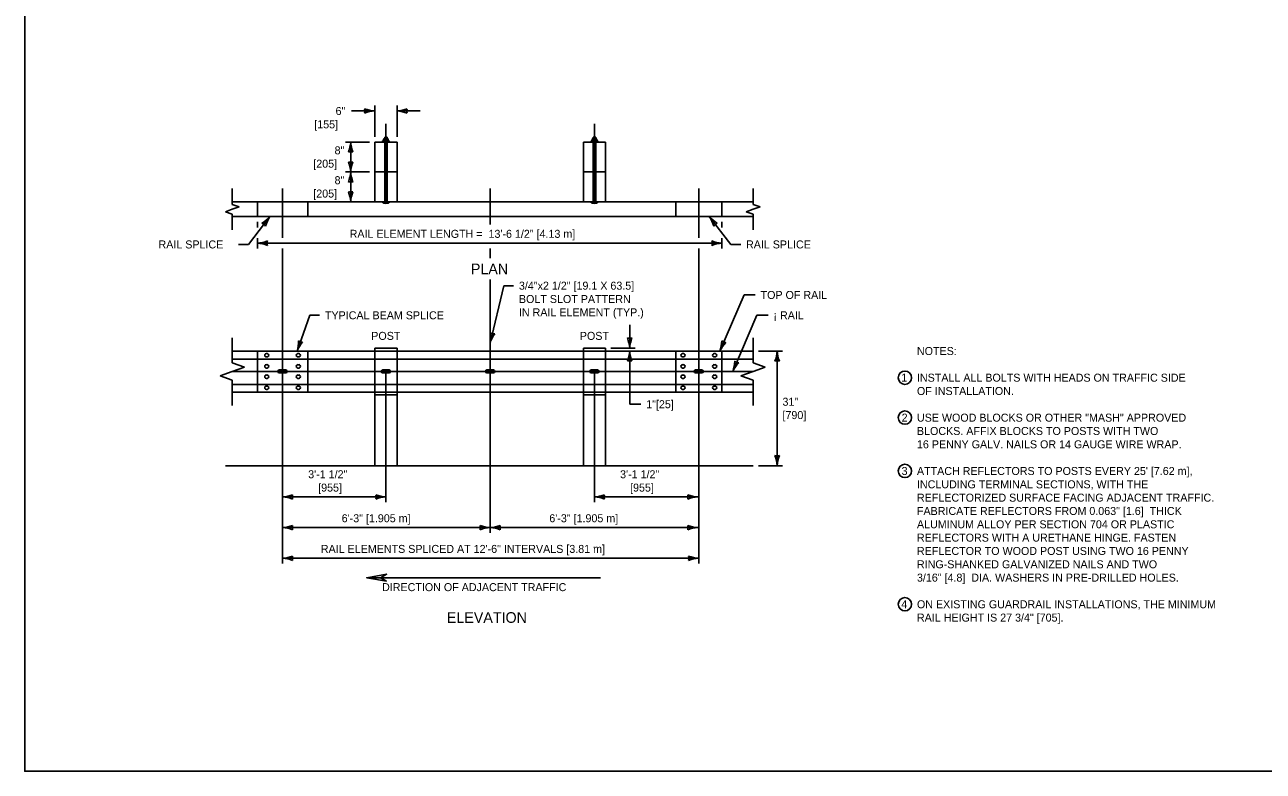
# Model space of a CAD drawing. Extents: x 49991.4 to 50021, y 49987.6 to 50011.4.
# Drawn here: x 49999.38 to 50008.67, y 49987.8 to 49993.4 of the extents above; entities that cross this region are included whole.
import ezdxf

# ---------------------------------------------------------------- set-up
doc = ezdxf.new("R2010")
doc.units = 0
for name, color, linetype in [('Level 1', 7, 'Continuous'), ('Level 2', 7, 'Continuous'), ('Level 3', 7, 'Continuous'), ('Level 4', 7, 'Continuous'), ('Level 5', 7, 'Continuous'), ('Level 6', 7, 'Continuous')]:
    doc.layers.add(name, color=color, linetype=linetype)

msp = doc.modelspace()

# ---------------------------------------------------------------- linework, layer by layer
at = {"layer": 'Level 1'}
for p, q in [((50002.008, 49992.0707), (50002.008, 49992.5187)), ((50002.1746, 49992.5187), (50002.008, 49992.5187)), ((50002.1158, 49992.5278), (50002.067, 49992.5278)), ((50002.067, 49992.5278), (50002.067, 49992.5187)), ((50002.0733, 49992.5278), (50002.0733, 49992.5412)), ((50002.1045, 49992.5439), (50002.0784, 49992.544)), ((50002.1005, 49992.5554), (50002.0822, 49992.5554)), ((50002.0822, 49992.544), (50002.0822, 49992.5554)), ((50002.1005, 49992.5543), (50002.0822, 49992.5534)), ((50002.1005, 49992.5502), (50002.0822, 49992.5493)), ((50002.1005, 49992.5466), (50002.0822, 49992.5457)), ((50002.0834, 49992.5278), (50002.0834, 49992.5413)), ((50002.0996, 49992.5278), (50002.0996, 49992.5414)), ((50002.1005, 49992.5439), (50002.1005, 49992.5554)), ((50002.1095, 49992.5415), (50002.1095, 49992.5278)), ((50002.1158, 49992.5278), (50002.1158, 49992.5187)), ((50002.1746, 49992.0707), (50002.1746, 49992.5187)), ((50003.5719, 49992.0707), (50003.5719, 49992.5187)), ((50003.5719, 49992.5187), (50003.7385, 49992.5187)), ((50003.6307, 49992.5278), (50003.6795, 49992.5278)), ((50003.6307, 49992.5278), (50003.6307, 49992.5187)), ((50003.637, 49992.5415), (50003.637, 49992.5278)), ((50003.6419, 49992.5439), (50003.668, 49992.544)), ((50003.646, 49992.5554), (50003.6643, 49992.5554)), ((50003.646, 49992.5439), (50003.646, 49992.5554)), ((50003.646, 49992.5543), (50003.6643, 49992.5534)), ((50003.646, 49992.5502), (50003.6643, 49992.5493)), ((50003.646, 49992.5466), (50003.6643, 49992.5457)), ((50003.6469, 49992.5278), (50003.6469, 49992.5414)), ((50003.663, 49992.5278), (50003.663, 49992.5413)), ((50003.6643, 49992.544), (50003.6643, 49992.5554)), ((50003.6732, 49992.5278), (50003.6732, 49992.5412)), ((50003.6795, 49992.5278), (50003.6795, 49992.5187)), ((50003.7385, 49992.0707), (50003.7385, 49992.5187)), ((50002.1746, 49992.2947), (50002.008, 49992.2947)), ((50003.5719, 49992.2947), (50003.7385, 49992.2947)), ((50000.9397, 49992.0707), (50004.8443, 49992.0707)), ((50001.1274, 49992.0707), (50001.1274, 49991.9597)), ((50004.2645, 49992.0707), (50004.2645, 49991.9597)), ((50000.9397, 49991.9597), (50004.8443, 49991.9597)), ((50004.8443, 49990.9514), (50000.9397, 49990.9514)), ((50001.1274, 49990.6438), (50001.1274, 49990.9514)), ((50001.201, 49990.9321), (50001.195, 49990.9321)), ((50001.201, 49990.9069), (50001.195, 49990.9069)), ((50001.4381, 49990.9321), (50001.4321, 49990.9321)), ((50001.4381, 49990.9069), (50001.4321, 49990.9069)), ((50002.1747, 49990.9734), (50002.0081, 49990.9734)), ((50002.0081, 49990.9734), (50002.0081, 49990.9514)), ((50002.1747, 49990.9734), (50002.1747, 49990.9514)), ((50003.7384, 49990.9734), (50003.5718, 49990.9734)), ((50003.5718, 49990.9734), (50003.5718, 49990.9514)), ((50003.7384, 49990.9734), (50003.7384, 49990.9514)), ((50004.2645, 49990.6438), (50004.2645, 49990.9514)), ((50004.322, 49990.9321), (50004.316, 49990.9321)), ((50004.322, 49990.9069), (50004.316, 49990.9069)), ((50004.5591, 49990.9321), (50004.5531, 49990.9321)), ((50004.5591, 49990.9069), (50004.5531, 49990.9069)), ((50004.8443, 49990.8913), (50000.9397, 49990.8913)), ((50001.201, 49990.8489), (50001.195, 49990.8489)), ((50001.201, 49990.8238), (50001.195, 49990.8238)), ((50001.2918, 49990.8092), (50001.3404, 49990.8092)), ((50001.4381, 49990.8489), (50001.4321, 49990.8489)), ((50001.4381, 49990.8238), (50001.4321, 49990.8238)), ((50002.0671, 49990.8092), (50002.1157, 49990.8092)), ((50002.8488, 49990.8092), (50002.8975, 49990.8092)), ((50003.6306, 49990.8092), (50003.6792, 49990.8092)), ((50004.322, 49990.8489), (50004.316, 49990.8489)), ((50004.322, 49990.8238), (50004.316, 49990.8238)), ((50004.4128, 49990.8092), (50004.4614, 49990.8092)), ((50004.5591, 49990.8489), (50004.5531, 49990.8489)), ((50004.5591, 49990.8238), (50004.5531, 49990.8238)), ((50001.201, 49990.7714), (50001.195, 49990.7714)), ((50001.201, 49990.7463), (50001.195, 49990.7463)), ((50001.2918, 49990.7884), (50001.3404, 49990.7884)), ((50001.4381, 49990.7714), (50001.4321, 49990.7714)), ((50001.4381, 49990.7463), (50001.4321, 49990.7463)), ((50002.0671, 49990.7884), (50002.1157, 49990.7884)), ((50002.8488, 49990.7884), (50002.8975, 49990.7884)), ((50003.6306, 49990.7884), (50003.6792, 49990.7884)), ((50004.322, 49990.7714), (50004.316, 49990.7714)), ((50004.322, 49990.7463), (50004.316, 49990.7463)), ((50004.4128, 49990.7884), (50004.4614, 49990.7884)), ((50004.5591, 49990.7714), (50004.5531, 49990.7714)), ((50004.5591, 49990.7463), (50004.5531, 49990.7463)), ((50004.8443, 49990.7013), (50000.9397, 49990.7013)), ((50004.8443, 49990.6438), (50000.9397, 49990.6438)), ((50001.201, 49990.6883), (50001.195, 49990.6883)), ((50001.201, 49990.6631), (50001.195, 49990.6631)), ((50001.4381, 49990.6883), (50001.4321, 49990.6883)), ((50001.4381, 49990.6631), (50001.4321, 49990.6631)), ((50002.0081, 49990.6438), (50002.0081, 49990.0903)), ((50002.1747, 49990.6218), (50002.0081, 49990.6218)), ((50002.1747, 49990.6438), (50002.1747, 49990.0903)), ((50003.5718, 49990.6438), (50003.5718, 49990.0903)), ((50003.7384, 49990.6218), (50003.5718, 49990.6218)), ((50003.7384, 49990.6438), (50003.7384, 49990.0903)), ((50004.322, 49990.6883), (50004.316, 49990.6883)), ((50004.322, 49990.6631), (50004.316, 49990.6631)), ((50004.5591, 49990.6883), (50004.5531, 49990.6883)), ((50004.5591, 49990.6631), (50004.5531, 49990.6631)), ((50000.8893, 49990.0903), (50004.8443, 49990.0903))]:
    msp.add_line(p, q, dxfattribs=at)
msp.add_lwpolyline([(49999.3835, 49998.9992), (50016.7501, 49998.9992), (50016.7501, 49987.7988), (49999.3835, 49987.7988)], close=True, dxfattribs=at)
for centre, radius, start, end in [((50002.0784, 49992.5379), 0.00606, 33.88707, 147.47731), ((50002.0915, 49992.5301), 0.0138, 54.60759, 125.9383), ((50002.1046, 49992.5377), 0.00626, 38.23957, 143.50603), ((50003.6419, 49992.5377), 0.00626, 36.49397, 141.76043), ((50003.6549, 49992.5301), 0.0138, 54.0617, 125.39241), ((50003.6681, 49992.5379), 0.00606, 32.52269, 146.11293), ((50001.2918, 49990.7988), 0.0104, 90, 180), ((50001.3404, 49990.7988), 0.0104, 360, 90), ((50002.0671, 49990.7988), 0.0104, 90, 180), ((50002.1157, 49990.7988), 0.0104, 360, 90), ((50002.8488, 49990.7988), 0.0104, 90, 180), ((50002.8975, 49990.7988), 0.0104, 360, 90), ((50003.6306, 49990.7988), 0.0104, 90, 180), ((50003.6792, 49990.7988), 0.0104, 360, 90), ((50004.4128, 49990.7988), 0.0104, 90, 180), ((50004.4614, 49990.7988), 0.0104, 360, 90), ((50001.2918, 49990.7988), 0.0104, 180, 270), ((50001.3404, 49990.7988), 0.0104, 270, 0), ((50002.0671, 49990.7988), 0.0104, 180, 270), ((50002.1157, 49990.7988), 0.0104, 270, 0), ((50002.8488, 49990.7988), 0.0104, 180, 270), ((50002.8975, 49990.7988), 0.0104, 270, 0), ((50003.6306, 49990.7988), 0.0104, 180, 270), ((50003.6792, 49990.7988), 0.0104, 270, 0), ((50004.4128, 49990.7988), 0.0104, 180, 270), ((50004.4614, 49990.7988), 0.0104, 270, 0)]:
    msp.add_arc(centre, radius, start, end, dxfattribs=at)
for centre, start_param, end_param in [((50001.195, 49990.9195), 1.570796, 4.712389), ((50001.201, 49990.9195), 4.712389, 7.853982), ((50001.4321, 49990.9195), 1.570796, 4.712389), ((50001.4381, 49990.9195), 4.712389, 7.853982), ((50004.316, 49990.9195), 1.570796, 4.712389), ((50004.322, 49990.9195), 4.712389, 7.853982), ((50004.5531, 49990.9195), 1.570796, 4.712389), ((50004.5591, 49990.9195), 4.712389, 7.853982), ((50001.195, 49990.8364), 1.570796, 4.712389), ((50001.201, 49990.8364), 4.712389, 7.853982), ((50001.4321, 49990.8364), 1.570796, 4.712389), ((50001.4381, 49990.8364), 4.712389, 7.853982), ((50004.316, 49990.8364), 1.570796, 4.712389), ((50004.322, 49990.8364), 4.712389, 7.853982), ((50004.5531, 49990.8364), 1.570796, 4.712389), ((50004.5591, 49990.8364), 4.712389, 7.853982), ((50001.195, 49990.7589), 1.570796, 4.712389), ((50001.201, 49990.7589), 4.712389, 7.853982), ((50001.4321, 49990.7589), 1.570796, 4.712389), ((50001.4381, 49990.7589), 4.712389, 7.853982), ((50004.316, 49990.7589), 1.570796, 4.712389), ((50004.322, 49990.7589), 4.712389, 7.853982), ((50004.5531, 49990.7589), 1.570796, 4.712389), ((50004.5591, 49990.7589), 4.712389, 7.853982), ((50001.195, 49990.6757), 1.570796, 4.712389), ((50001.201, 49990.6757), 4.712389, 7.853982), ((50001.4321, 49990.6757), 1.570796, 4.712389), ((50001.4381, 49990.6757), 4.712389, 7.853982), ((50004.316, 49990.6757), 1.570796, 4.712389), ((50004.322, 49990.6757), 4.712389, 7.853982), ((50004.5531, 49990.6757), 1.570796, 4.712389), ((50004.5591, 49990.6757), 4.712389, 7.853982)]:
    msp.add_ellipse(centre, major_axis=(0.0126, 0), ratio=0.998676, start_param=start_param, end_param=end_param, dxfattribs=at)
at = {"layer": 'Level 2'}
for centre in [(50005.9833, 49990.7514), (50005.9833, 49990.4515), (50005.9833, 49990.0514), (50005.9833, 49989.0514)]:
    msp.add_circle(centre, 0.05, dxfattribs=at)
at = {"layer": 'Level 3'}
for p, q in [((50002.008, 49992.5587), (50002.008, 49992.7921)), ((50002.1746, 49992.5587), (50002.1746, 49992.7921)), ((50001.8346, 49992.7521), (50002.008, 49992.7521)), ((50002.1746, 49992.7521), (50002.348, 49992.7521)), ((50001.9681, 49992.5187), (50001.7873, 49992.5187)), ((50001.8273, 49992.5187), (50001.8273, 49992.2947)), ((50001.9681, 49992.2947), (50001.7872, 49992.2947)), ((50001.8273, 49992.2947), (50001.8273, 49992.0707)), ((50001.0608, 49991.751), (50001.2221, 49991.9597)), ((50001.1274, 49991.9197), (50001.1274, 49991.8772)), ((50004.6777, 49991.751), (50004.5164, 49991.9597)), ((50004.6111, 49991.9197), (50004.6111, 49991.8772)), ((50000.9867, 49991.751), (50001.0608, 49991.751)), ((50001.1274, 49991.7972), (50001.1274, 49991.7205)), ((50001.1274, 49991.7605), (50004.6111, 49991.7605)), ((50004.6111, 49991.7972), (50004.6111, 49991.7205)), ((50004.7517, 49991.751), (50004.6777, 49991.751)), ((50002.9748, 49991.4415), (50002.8732, 49991.0106)), ((50003.0489, 49991.4415), (50002.9748, 49991.4415)), ((50004.7768, 49991.3719), (50004.5952, 49990.9514)), ((50004.8608, 49991.3719), (50004.7768, 49991.3719)), ((50001.5203, 49991.2193), (50001.4255, 49990.9514)), ((50001.5942, 49991.2193), (50001.5203, 49991.2193)), ((50004.8734, 49991.2193), (50004.6918, 49990.7988)), ((50004.9574, 49991.2193), (50004.8734, 49991.2193)), ((50003.9193, 49990.9734), (50003.9193, 49991.1468)), ((50003.7784, 49990.9734), (50003.9593, 49990.9734)), ((50003.9193, 49990.9514), (50003.9193, 49990.5523)), ((50004.8843, 49990.9514), (50005.0651, 49990.9514)), ((50005.0251, 49990.0903), (50005.0251, 49990.9514)), ((50005.0251, 49990.681), (50005.0251, 49990.0903)), ((50004.0033, 49990.5523), (50003.9193, 49990.5523)), ((50004.8843, 49990.0903), (50005.0651, 49990.0903)), ((50001.3161, 49989.8567), (50002.0914, 49989.8567)), ((50004.4302, 49989.8567), (50003.6549, 49989.8567)), ((50001.3161, 49989.6267), (50002.8732, 49989.6267)), ((50002.8732, 49989.6267), (50004.4302, 49989.6267)), ((50001.3161, 49989.3967), (50004.4371, 49989.3967)), ((50003.701, 49989.2499), (50001.9479, 49989.2499))]:
    msp.add_line(p, q, dxfattribs=at)
msp.add_lwpolyline([(50002.0968, 49989.2237), (50001.9479, 49989.2499), (50002.0968, 49989.2763), (50002.0514, 49989.2499)], close=True, dxfattribs=at)
for centre, radius, start, end in [((50001.8798, 49992.7521), 0.0548, 342.13882, 17.86118), ((50002.0195, 49992.9848), 0.233, 247.92284, 267.17269), ((50002.1654, 49992.9742), 0.2223, 272.36048, 292.54399), ((50002.3028, 49992.7521), 0.0548, 162.13882, 197.86118), ((50002.0171, 49992.53), 0.2223, 92.36048, 112.54399), ((50002.1631, 49992.5194), 0.233, 67.92284, 87.17269), ((50001.5945, 49992.5302), 0.233, 337.92284, 357.17269), ((50002.0494, 49992.5278), 0.2223, 182.36048, 202.54399), ((50001.8273, 49992.3904), 0.0548, 72.13882, 107.86118), ((50001.6051, 49992.2855), 0.2223, 2.36048, 22.54399), ((50001.8273, 49992.4229), 0.0548, 252.13882, 287.86118), ((50001.5945, 49992.3062), 0.233, 337.92284, 357.17269), ((50002.06, 49992.2832), 0.233, 157.92284, 177.17269), ((50002.0494, 49992.3039), 0.2223, 182.36048, 202.54399), ((50001.8273, 49992.1665), 0.0548, 72.13882, 107.86118), ((50001.6051, 49992.0615), 0.2223, 2.36048, 22.54399), ((50001.8273, 49992.1989), 0.0548, 252.13882, 287.86118), ((50002.06, 49992.0592), 0.233, 157.92284, 177.17269), ((50001.0519, 49992.1028), 0.2223, 299.76567, 319.94918), ((50001.4132, 49991.8265), 0.233, 145.13698, 164.38683), ((50004.6866, 49992.1028), 0.2223, 220.05082, 240.23433), ((50004.3252, 49991.8265), 0.233, 15.61318, 34.86303), ((50001.1437, 49991.8582), 0.0548, 34.44848, 70.17084), ((50004.5948, 49991.8582), 0.0548, 109.82916, 145.55152), ((50001.1159, 49991.9932), 0.233, 272.82731, 292.07716), ((50001.1182, 49991.5384), 0.2223, 67.45601, 87.63952), ((50001.2556, 49991.7605), 0.0548, 162.13882, 197.86118), ((50004.6202, 49991.9827), 0.2223, 247.45601, 267.63952), ((50004.4829, 49991.7605), 0.0548, 342.13882, 17.86118), ((50004.6226, 49991.5278), 0.233, 92.82731, 112.07716), ((50002.644, 49991.0528), 0.233, 349.54916, 8.79901), ((50002.9026, 49991.1354), 0.0548, 238.86066, 274.58303), ((50001.2023, 49991.0182), 0.233, 343.34031, 2.59016), ((50001.6318, 49990.8687), 0.2223, 137.96901, 158.15251), ((50001.4683, 49991.0723), 0.0548, 232.65181, 268.37417), ((50003.0872, 49990.9506), 0.2223, 144.17786, 164.36136), ((50003.6971, 49990.9642), 0.2223, 2.36048, 22.54399), ((50003.9193, 49991.1016), 0.0548, 252.13882, 287.86118), ((50004.152, 49990.9619), 0.233, 157.92284, 177.17269), ((50004.377, 49991.0331), 0.233, 339.4694, 358.71925), ((50004.7955, 49990.8549), 0.2223, 134.0981, 154.28161), ((50004.6461, 49991.0691), 0.0548, 228.78091, 264.50327), ((50003.6971, 49990.9606), 0.2223, 337.45601, 357.63952), ((50004.152, 49990.9629), 0.233, 182.82731, 202.07716), ((50004.803, 49990.9606), 0.2223, 337.45601, 357.63952), ((50005.2578, 49990.9629), 0.233, 182.82731, 202.07716), ((50003.9193, 49990.8232), 0.0548, 72.13882, 107.86118), ((50004.4736, 49990.8805), 0.233, 339.4694, 358.71925), ((50004.8921, 49990.7023), 0.2223, 134.0981, 154.28161), ((50004.7426, 49990.9165), 0.0548, 228.78091, 264.50327), ((50005.0251, 49990.8232), 0.0548, 72.13882, 107.86118), ((50005.0251, 49990.2185), 0.0548, 252.13882, 287.86118), ((50004.7924, 49990.0788), 0.233, 2.82731, 22.07716), ((50005.2472, 49990.0811), 0.2223, 157.45601, 177.63952), ((50001.3046, 49990.0894), 0.233, 272.82731, 292.07716), ((50001.3069, 49989.6346), 0.2223, 67.45601, 87.63952), ((50001.4443, 49989.8567), 0.0548, 162.13882, 197.86118), ((50002.1006, 49990.0788), 0.2223, 247.45601, 267.63952), ((50001.9632, 49989.8567), 0.0548, 342.13882, 17.86118), ((50002.1029, 49989.624), 0.233, 92.82731, 112.07716), ((50003.6457, 49990.0788), 0.2223, 272.36048, 292.54399), ((50003.6434, 49989.624), 0.233, 67.92284, 87.17269), ((50003.7831, 49989.8567), 0.0548, 162.13882, 197.86118), ((50004.302, 49989.8567), 0.0548, 342.13882, 17.86118), ((50004.4417, 49990.0894), 0.233, 247.92284, 267.17269), ((50004.4394, 49989.6346), 0.2223, 92.36048, 112.54399), ((50001.3046, 49989.8594), 0.233, 272.82731, 292.07716), ((50001.3069, 49989.4046), 0.2223, 67.45601, 87.63952), ((50001.4443, 49989.6267), 0.0548, 162.13882, 197.86118), ((50002.8823, 49989.8488), 0.2223, 247.45601, 267.63952), ((50002.7449, 49989.6267), 0.0548, 342.13882, 17.86118), ((50002.8846, 49989.394), 0.233, 92.82731, 112.07716), ((50002.8617, 49989.8594), 0.233, 272.82731, 292.07716), ((50002.864, 49989.4046), 0.2223, 67.45601, 87.63952), ((50003.0014, 49989.6267), 0.0548, 162.13882, 197.86118), ((50004.4394, 49989.8488), 0.2223, 247.45601, 267.63952), ((50004.302, 49989.6267), 0.0548, 342.13882, 17.86118), ((50004.4417, 49989.394), 0.233, 92.82731, 112.07716), ((50001.3046, 49989.6294), 0.233, 272.82731, 292.07716), ((50001.4443, 49989.3967), 0.0548, 162.13882, 197.86118), ((50004.4462, 49989.6188), 0.2223, 247.45601, 267.63952), ((50004.3089, 49989.3967), 0.0548, 342.13882, 17.86118), ((50001.3069, 49989.1746), 0.2223, 67.45601, 87.63952), ((50004.4486, 49989.164), 0.233, 92.82731, 112.07716)]:
    msp.add_arc(centre, radius, start, end, dxfattribs=at)
at = {"layer": 'Level 4'}
for p, q in [((50002.0822, 49992.0707), (50002.0822, 49992.5187)), ((50002.1005, 49992.0707), (50002.1005, 49992.5187)), ((50003.646, 49992.0707), (50003.646, 49992.5187)), ((50003.6643, 49992.0707), (50003.6643, 49992.5187)), ((50001.5048, 49992.0707), (50001.5048, 49991.9597)), ((50004.6111, 49991.9597), (50004.6111, 49992.0707)), ((50001.5048, 49990.6438), (50001.5048, 49990.9514)), ((50002.0081, 49990.6438), (50002.0081, 49990.9514)), ((50002.1747, 49990.6438), (50002.1747, 49990.952)), ((50003.5718, 49990.6438), (50003.5718, 49990.9514)), ((50003.7384, 49990.6438), (50003.7384, 49990.952)), ((50004.6111, 49990.6438), (50004.6111, 49990.9514))]:
    msp.add_line(p, q, dxfattribs=at)
for centre in [(50002.0915, 49992.1026), (50003.655, 49992.1026)]:
    msp.add_arc(centre, 0.0442, 226.30804, 313.69196, dxfattribs=at)
at = {"layer": 'Level 5'}
for p, q in [((50002.0913, 49992.0707), (50002.0914, 49992.6554)), ((50003.6551, 49992.0707), (50003.6551, 49992.6554)), ((50001.3161, 49991.8005), (50001.3161, 49992.1707)), ((50002.8733, 49991.9005), (50002.8732, 49992.1707)), ((50004.4371, 49991.8005), (50004.4371, 49992.1707)), ((50001.3161, 49989.3567), (50001.3161, 49991.7205)), ((50002.8733, 49991.6471), (50002.8733, 49991.7205)), ((50004.4371, 49989.3567), (50004.4371, 49991.7205)), ((50002.8732, 49989.5867), (50002.8732, 49991.4871)), ((50004.8477, 49990.7988), (50000.9431, 49990.7988)), ((50002.0914, 49989.8167), (50002.0914, 49990.7988)), ((50003.6549, 49989.8167), (50003.6549, 49990.7988))]:
    msp.add_line(p, q, dxfattribs=at)
at = {"layer": 'Level 6'}
for p, q in [((50000.9397, 49992.1707), (50000.9397, 49992.0518)), ((50004.8443, 49992.1707), (50004.8443, 49992.0518)), ((50000.9397, 49992.0147), (50000.8874, 49991.9962)), ((50000.9921, 49992.0333), (50000.9397, 49992.0518)), ((50000.9921, 49992.0333), (50000.9397, 49992.0147)), ((50004.8443, 49992.0147), (50004.792, 49991.9962)), ((50004.8967, 49992.0333), (50004.8443, 49992.0518)), ((50004.8967, 49992.0333), (50004.8443, 49992.0147)), ((50000.9397, 49991.9776), (50000.8874, 49991.9962)), ((50000.9397, 49991.9776), (50000.9397, 49991.8597)), ((50004.8443, 49991.9776), (50004.792, 49991.9962)), ((50004.8443, 49991.9776), (50004.8443, 49991.8597)), ((50000.9397, 49991.0514), (50000.9397, 49990.8624)), ((50004.8443, 49991.0514), (50004.8443, 49990.8624)), ((50001.0311, 49990.83), (50000.9397, 49990.8624)), ((50001.0311, 49990.83), (50000.9397, 49990.7976)), ((50004.9357, 49990.83), (50004.8443, 49990.8624)), ((50004.9357, 49990.83), (50004.8443, 49990.7976)), ((50000.9397, 49990.7976), (50000.8483, 49990.7652)), ((50000.9397, 49990.7328), (50000.8483, 49990.7652)), ((50000.9397, 49990.7328), (50000.9397, 49990.5438)), ((50004.8443, 49990.7976), (50004.7529, 49990.7652)), ((50004.8443, 49990.7328), (50004.7529, 49990.7652)), ((50004.8443, 49990.7328), (50004.8443, 49990.5438))]:
    msp.add_line(p, q, dxfattribs=at)

# ---------------------------------------------------------------- texts
at = {"layer": 'Level 2'}
for s, height, p in [('6"', 0.06, (50001.7139, 49992.7221)), ('[155]', 0.06, (50001.5541, 49992.6221)), ('8"', 0.06, (50001.7066, 49992.4267)), ('[205]', 0.06, (50001.5468, 49992.3267)), ('8"', 0.06, (50001.7066, 49992.2027)), ('[205]', 0.06, (50001.5468, 49992.1027)), ('RAIL ELEMENT LENGTH =  13\'-6 1/2" [4.13 m]', 0.06, (50001.8196, 49991.8005)), ('RAIL SPLICE', 0.06, (50000.3863, 49991.721)), ('RAIL SPLICE', 0.06, (50004.7917, 49991.721)), ('PLAN', 0.08, (50002.7284, 49991.5271)), ('3/4"x2 1/2" [19.1 X 63.5]', 0.06, (50003.0889, 49991.4115)), ('BOLT SLOT PATTERN', 0.06, (50003.0889, 49991.3115)), ('TOP OF RAIL', 0.06, (50004.9008, 49991.3419)), ('IN RAIL ELEMENT (TYP.)', 0.06, (50003.0889, 49991.2115)), ('TYPICAL BEAM SPLICE', 0.06, (50001.6342, 49991.1893)), ('¡ RAIL', 0.06, (50004.9974, 49991.1893)), ('POST', 0.06, (50001.9816, 49991.0349)), ('POST', 0.06, (50003.5455, 49991.0349)), ('NOTES:', 0.06, (50006.0733, 49990.9214)), ('1', 0.06, (50005.9558, 49990.7214)), ('INSTALL ALL BOLTS WITH HEADS ON TRAFFIC SIDE ', 0.06, (50006.0733, 49990.7214)), ('OF INSTALLATION.', 0.06, (50006.0733, 49990.6214)), ('1"[25]', 0.06, (50004.0433, 49990.5223)), ('31"', 0.06, (50005.0651, 49990.5408)), ('[790]', 0.06, (50005.0651, 49990.4408)), ('2', 0.06, (50005.9582, 49990.4215)), ('USE WOOD BLOCKS OR OTHER "MASH" APPROVED ', 0.06, (50006.0733, 49990.4214)), ('BLOCKS. AFFIX BLOCKS TO POSTS WITH TWO ', 0.06, (50006.0733, 49990.3214)), ('16 PENNY GALV. NAILS OR 14 GAUGE WIRE WRAP.', 0.06, (50006.0733, 49990.2214)), ('3', 0.06, (50005.9582, 49990.0216)), ("ATTACH REFLECTORS TO POSTS EVERY 25' [7.62 m],", 0.06, (50006.0733, 49990.0214)), ('3\'-1 1/2" ', 0.06, (50001.5086, 49989.9967)), ('3\'-1 1/2" ', 0.06, (50003.8474, 49989.9967)), ('INCLUDING TERMINAL SECTIONS, WITH THE ', 0.06, (50006.0733, 49989.9214)), ('[955]', 0.06, (50001.5835, 49989.8967)), ('[955]', 0.06, (50003.9223, 49989.8967)), ('REFLECTORIZED SURFACE FACING ADJACENT TRAFFIC.  ', 0.06, (50006.0733, 49989.8214)), ('FABRICATE REFLECTORS FROM 0.063" [1.6]  THICK ', 0.06, (50006.0733, 49989.7214)), ('6\'-3" [1.905 m]', 0.06, (50001.7597, 49989.6667)), ('6\'-3" [1.905 m]', 0.06, (50003.3167, 49989.6667)), ('ALUMINUM ALLOY PER SECTION 704 OR PLASTIC', 0.06, (50006.0733, 49989.6214)), ('REFLECTORS WITH A URETHANE HINGE. FASTEN ', 0.06, (50006.0733, 49989.5214)), ('RAIL ELEMENTS SPLICED AT 12\'-6" INTERVALS [3.81 m]', 0.06, (50001.6035, 49989.4367)), ('REFLECTOR TO WOOD POST USING TWO 16 PENNY', 0.06, (50006.0733, 49989.4214)), ('RING-SHANKED GALVANIZED NAILS AND TWO', 0.06, (50006.0733, 49989.3214)), ('3/16" [4.8]  DIA. WASHERS IN PRE-DRILLED HOLES.', 0.06, (50006.0733, 49989.2214)), ('DIRECTION OF ADJACENT TRAFFIC', 0.06, (50002.0625, 49989.1499)), ('4', 0.06, (50005.9557, 49989.0214)), ('ON EXISTING GUARDRAIL INSTALLATIONS, THE MINIMUM ', 0.06, (50006.0733, 49989.0214)), ('ELEVATION', 0.08, (50002.5484, 49988.9121)), ('RAIL HEIGHT IS 27 3/4" [705].', 0.06, (50006.0733, 49988.9214))]:
    msp.add_text(s, height=height, dxfattribs=at).set_placement(p)

doc.saveas('drawing.dxf')
